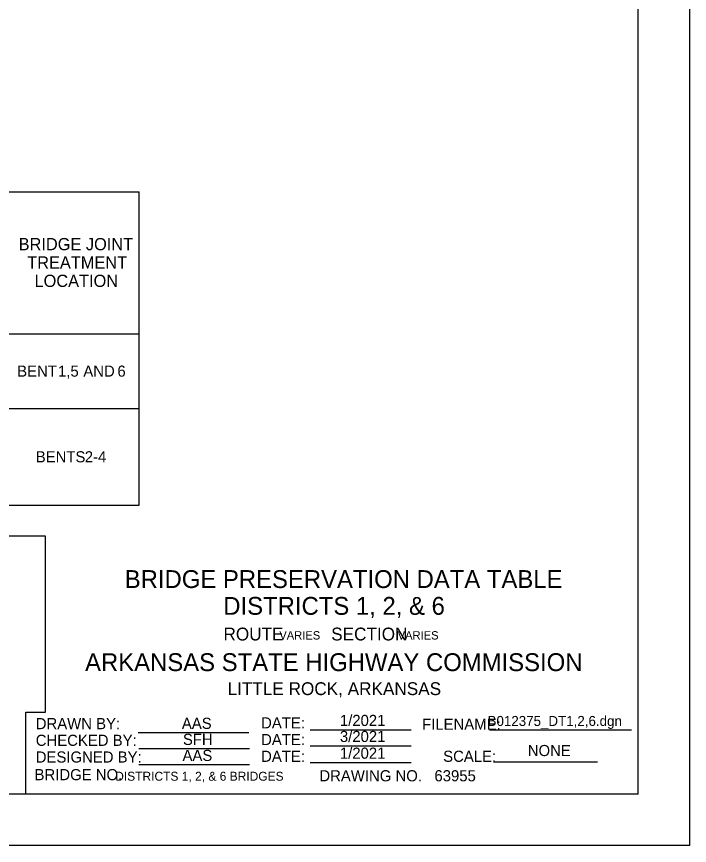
# Model space of a CAD drawing. Extents: x 16 to 1228740, y 11 to 152440.
# Drawn here: x 17.861 to 18.49, y 10.709 to 11.485 of the extents above; entities that cross this region are included whole.
import ezdxf

# ---------------------------------------------------------------- set-up
doc = ezdxf.new("R2010")
doc.units = 0
for name, color, linetype in [('B_Copy In', 7, 'Continuous'), ('B_Text', 7, 'Continuous'), ('B_Title Text', 7, 'Continuous'), ('R_Border', 7, 'Continuous'), ('R_No Plot', 7, 'Continuous')]:
    doc.layers.add(name, color=color, linetype=linetype)

msp = doc.modelspace()

# ---------------------------------------------------------------- linework, layer by layer
at = {"layer": 'B_Text'}
for p, q in [((16.24983, 11.32083), (17.97565, 11.32083)), ((17.97565, 11.02779), (17.97565, 11.32083)), ((16.24983, 11.188), (17.97565, 11.188)), ((16.24983, 11.188), (17.97565, 11.188)), ((16.24983, 11.11803), (17.97565, 11.11803)), ((16.24983, 11.02779), (17.97565, 11.02779)), ((17.97449, 10.81515), (18.07809, 10.81515)), ((18.13559, 10.81765), (18.23009, 10.81765)), ((18.30318, 10.81765), (18.43623, 10.81765)), ((17.97509, 10.80015), (18.07869, 10.80015)), ((18.13559, 10.80265), (18.23009, 10.80265)), ((18.13559, 10.80265), (18.23009, 10.80265)), ((17.97509, 10.78515), (18.07869, 10.78515)), ((18.13559, 10.78703), (18.23009, 10.78703)), ((18.30706, 10.78765), (18.40419, 10.78765))]:
    msp.add_line(p, q, dxfattribs=at)
at = {"layer": 'R_Border'}
for q in [(18.44221, 12.49475), (15.78327, 10.75755)]:
    msp.add_line((18.44221, 10.75755), q, dxfattribs=at)
msp.add_lwpolyline([(15.65694, 12.54282), (18.49027, 12.54282), (18.49027, 10.70949), (15.65694, 10.70949)], close=True, dxfattribs=at)
at = {"layer": 'R_No Plot'}
for p, q in [((17.888, 10.99864), (17.47349, 10.99864)), ((17.888, 10.83424), (17.888, 10.99864)), ((17.86946, 10.83424), (17.888, 10.83424)), ((17.86946, 10.75755), (17.86946, 10.83424))]:
    msp.add_line(p, q, dxfattribs=at)

# ---------------------------------------------------------------- texts
at = {"layer": 'B_Copy In'}
for s, height, p in [('BRIDGE PRESERVATION DATA TABLE  ', 0.0167, (17.96204, 10.9502)), ('DISTRICTS 1, 2, & 6', 0.0167, (18.05423, 10.92515)), ('AAS', 0.0104, (18.0155, 10.81846)), ('1/2021', 0.0104, (18.16332, 10.82119)), ('B012375_DT1,2,6.dgn', 0.0093366, (18.30145, 10.82121)), ('SFH', 0.0104, (18.01647, 10.80346)), ('3/2021', 0.0104, (18.16332, 10.80619)), ('AAS', 0.0104, (18.0161, 10.78846)), ('1/2021', 0.0104, (18.16332, 10.79057)), ('NONE', 0.0104, (18.3391, 10.79302)), ('DISTRICTS 1, 2, & 6 BRIDGES', 0.0083776, (17.95313, 10.76999)), ('63955', 0.010417, (18.25173, 10.76944))]:
    msp.add_text(s, height=height, dxfattribs=at).set_placement(p)
at = {"layer": 'B_Text'}
for s, height, p in [('BRIDGE JOINT', 0.01144, (17.86279, 11.26605)), ('TREATMENT', 0.01144, (17.8708, 11.24889)), ('LOCATION', 0.01144, (17.87763, 11.23173)), ('BENT', 0.0104, (17.86145, 11.14782)), (' 1,5', 0.0104, (17.8958, 11.14782)), (' AND', 0.0104, (17.91946, 11.14782)), (' 6', 0.0104, (17.95131, 11.14782)), ('BENTS', 0.0104, (17.87884, 11.06771)), (' 2-4', 0.0104, (17.9208, 11.06771)), ('DRAWN BY:', 0.010417, (17.87879, 10.8182)), ('DATE:', 0.010417, (18.08959, 10.8189)), ('FILENAME:', 0.010417, (18.24018, 10.81765)), ('CHECKED BY:', 0.0104166, (17.87879, 10.80257)), ('DATE:', 0.010417, (18.08959, 10.80328)), ('DESIGNED BY:', 0.0104166, (17.87879, 10.78695)), ('DATE:', 0.010417, (18.08959, 10.78765)), ('SCALE:', 0.010417, (18.25989, 10.78765)), ('BRIDGE NO.', 0.010417, (17.87767, 10.77048)), ('DRAWING NO.', 0.0104166, (18.14412, 10.76942))]:
    msp.add_text(s, height=height, dxfattribs=at).set_placement(p)
at = {"layer": 'B_Title Text'}
for s, height, p in [('ROUTE          SECTION ', 0.012, (18.0544, 10.90115)), ('                VARIES                         VARIES', 0.0078, (18.06026, 10.90204)), ('ARKANSAS STATE HIGHWAY COMMISSION', 0.0167, (17.92492, 10.8725)), ('LITTLE ROCK, ARKANSAS', 0.012, (18.05823, 10.85007))]:
    msp.add_text(s, height=height, dxfattribs=at).set_placement(p)

doc.saveas('drawing.dxf')
